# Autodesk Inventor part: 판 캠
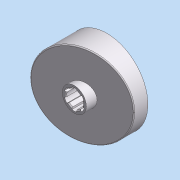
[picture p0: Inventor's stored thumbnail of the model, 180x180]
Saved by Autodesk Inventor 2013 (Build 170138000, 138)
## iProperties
Company: 한국ATC센터
Created: 2012-05
Part Number: 판 캠
Document SubType Name: 모델링
Designer: KYOUNG IL JANG
Mass: 681.587 g
Surface Area: 331.301 cm^2
Volume: 86.8263 cm^3
Density: 7.85 g/cm^3
Material: 강
변환 표준: STEP AP214IS
파일 이름: C:\Users\SeoGD\Desktop\?쒗뿕\??stp
전처리기: Build: 253, Release: 2010 SP1 - Date: Wed 07/29/2009
전송 단위: 밀리미터
불확실성: 0.01
Author: KYOUNG IL JANG
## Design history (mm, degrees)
node "작업 평면4"
sketch "스케치1"
  geometry: C1 r 44.5 at (0, 0); 1 further point
  constraints: 1 centre point, 1 coincident
  dimensions: "d25" = 89 diameter of C1
extrude "돌출1" new body sketch "스케치1" distance "d1" = 40; taper "d2" = 0 deg
sketch "스케치2"
  geometry: L1 (-44.5, 15)-(44.5, 38.847); L2 (-44.5, 0)-(-44.5, 40) reference; L3 (-44.5, 40)-(44.5, 40) reference; L4 (44.5, 0)-(44.5, 40) reference; 1 further point
  constraints: 2 end point, 2 point on line
  dimensions: "d26" = 15 distance of L2.start L1.start; "d27" = 75 deg angle of L1 L2
extrude "돌출2" cut sketch "스케치2" stored distance "d5" = 40; taper "d6" = 0 deg
node "작업 평면1"
sketch "스케치3"
  geometry: C1 r 13 at (0, 0); 1 further point
  constraints: 1 centre point, 1 coincident
  dimensions: "d9" = 26 diameter of C1
extrude "돌출3" join sketch "스케치3" distance "d10" = 38; taper "d11" = 0 deg
hole "구멍1" diameter "d14" = 18; stored, may be unused: countersink angle "d18" = 90 deg, drill point angle "d20" = 118 deg; dims "d12" = 10, "d13" = 10, "d15" = 6, "d16" = 4, "d17" = 2, "d19" = 8
feature "쉘2" dims "d29" = 5
sketch "스케치6"
  geometry: C1 r 17.5 at (0, 0); C2 r 14 at (0, 0) reference; 1 further point
  constraints: 1 centre point, 1 coincident
  dimensions: "d28" = 35 diameter of C1
extrude "돌출4" join sketch "스케치6" stored distance "d30" = 38; taper "d31" = 0 deg
fillet "모깎기1" dims "d32" = 3
chamfer "모따기1" distance "d21" = 1; stored, may be unused: second distance "d22" = 2, angle "d23" = 45 deg
sketch "스케치7"
  geometry: L1 (-12.374, 12.374)-(-27.931, 27.931); A1 r 39.5 centre (0, 0) between (-27.931, 27.931) and (0, 39.5) reference; 2 further points
  constraints: 2 end point, 2 point on circle, 1 point on line, 1 vertical alignment, 2 other
  dimensions: "d33" = 45 deg dimension on point (0, 0) L1.start A1.end
feature "리브1" sketch "스케치7" dims "d34" = 5, "d35" = 1, "d36" = 0
fillet "모깎기2" dims "d37" = 3
sketch "스케치8"
  geometry: L1 (2.5, 10.712)-(2.5, 8.646); L2 (-2.5, 10.712)-(-2.5, 8.646); A1 r 11 centre (0, 0) between (2.5, 10.712) and (-2.5, 10.712); A2 r 9 centre (0, 0) between (2.5, 8.646) and (-2.5, 8.646) reference; 1 further point
  constraints: 4 end point, 4 point on circle, 2 parallel, 1 centre point, 1 coincident, 1 vertical
  dimensions: "d41" = 22 diameter of A1; "d42" = 5 distance between parallel lines of L1 L2
extrude "돌출5" cut sketch "스케치8" stored distance "d43" = 38; taper "d44" = 0 deg
fillet "모깎기3" dims "d48" = 1
node "솔리드1"
node "솔리드 본체"
node "곡면 본체"
pattern_circular "원형 패턴1" dims angle "d39" = 360 deg
pattern_circular "원형 패턴2" dims angle "d46" = 360 deg
node "솔리드2"
